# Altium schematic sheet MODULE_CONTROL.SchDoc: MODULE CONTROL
size A3; Author: Silvio Navaretti; CompanyName: ARDUINO; Organization: ARDUINO; SheetNumber: 5; SheetTotal: 51; RevAuthor: Silvio Navaretti
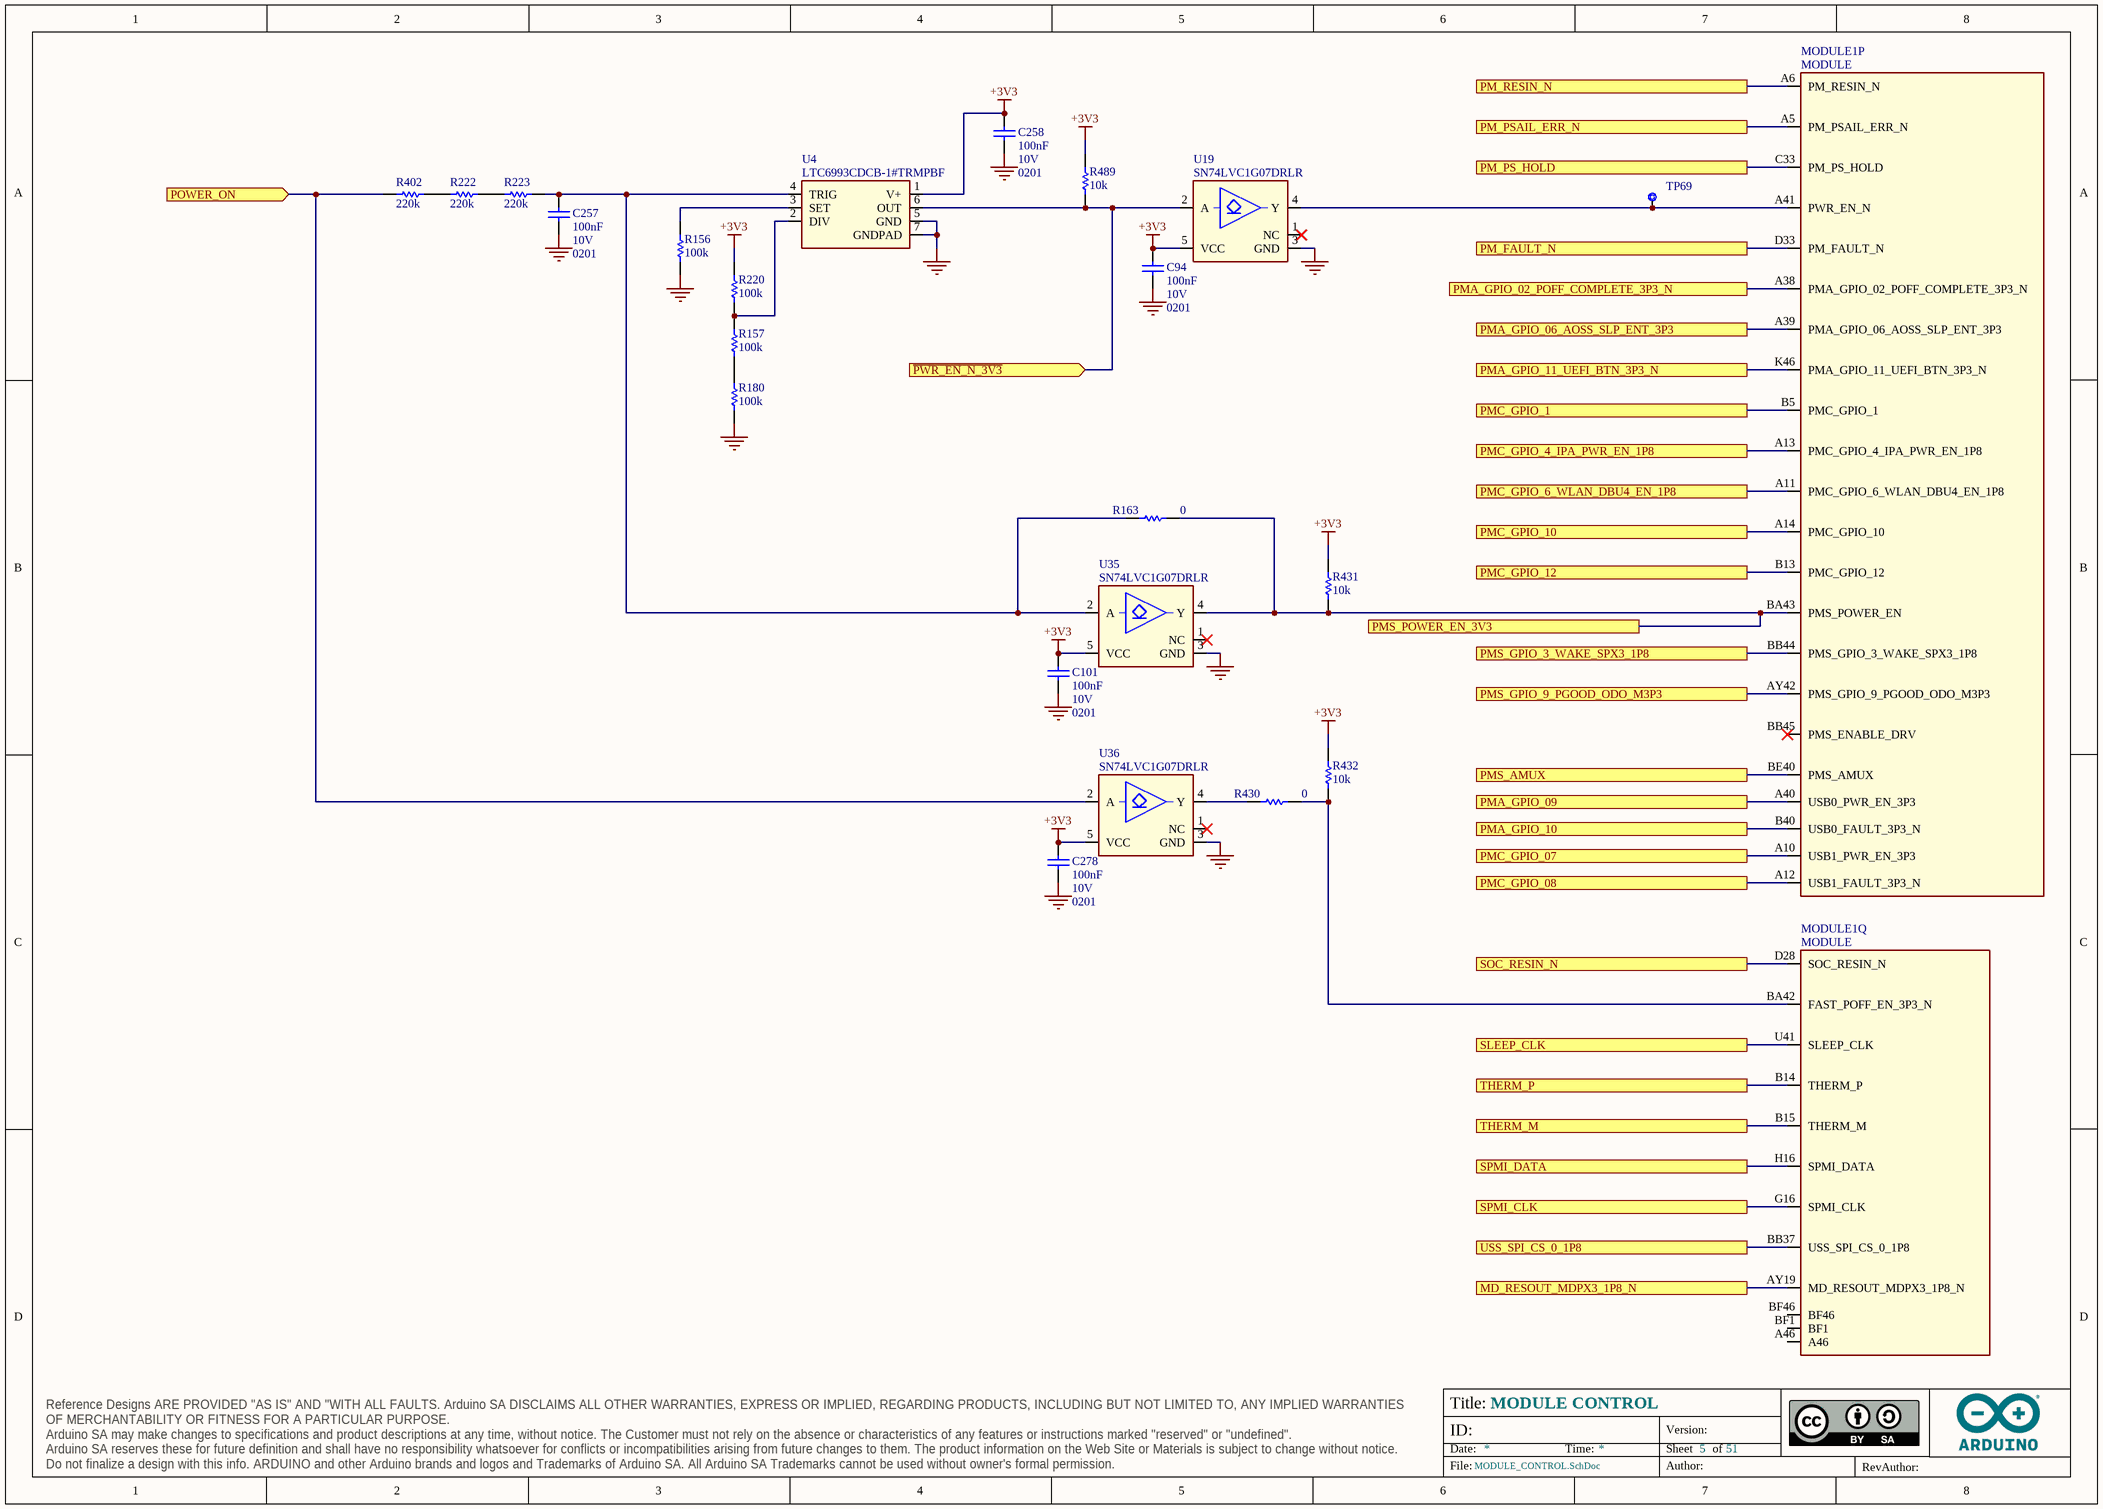
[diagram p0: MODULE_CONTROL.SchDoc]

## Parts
C94  value 100nF  Voltage: 10V  Case Code (Imperial): 0201  [CAP-0201]  (hidden comment: CL03A104KP3NNNC)
C101  value 100nF  Voltage: 10V  Case Code (Imperial): 0201  [CAP-0201]  (hidden comment: CL03A104KP3NNNC)
C257  value 100nF  Voltage: 10V  Case Code (Imperial): 0201  [CAP-0201]  (hidden comment: CL03A104KP3NNNC)
C258  value 100nF  Voltage: 10V  Case Code (Imperial): 0201  [CAP-0201]  (hidden comment: CL03A104KP3NNNC)
C278  value 100nF  Voltage: 10V  Case Code (Imperial): 0201  [CAP-0201]  (hidden comment: CL03A104KP3NNNC)
MODULE1  MODULE  [MODULE]  (parts P,Q of 22)
R156  value 100k  [RES-0201]  (hidden comment: RC0201FR-07100KL)
R157  value 100k  [RES-0201]  (hidden comment: RC0201FR-07100KL)
R163  value 0  [RES-0201]  (hidden comment: CRCW02010000Z0ED)
R180  value 100k  [RES-0201]  (hidden comment: RC0201FR-07100KL)
R220  value 100k  [RES-0201]  (hidden comment: RC0201FR-07100KL)
R222  value 220k  [RES-0201]  (hidden comment: AC0201FR-07220KL)
R223  value 220k  [RES-0201]  (hidden comment: AC0201FR-07220KL)
R402  value 220k  [RES-0201]  (hidden comment: AC0201FR-07220KL)
R430  value 0  [RES-0201]  (hidden comment: CRCW02010000Z0ED)
R431  value 10k  [RES-0201]  (hidden comment: RC0201FR-0710KL)
R432  value 10k  [RES-0201]  (hidden comment: RC0201FR-0710KL)
R489  value 10k  [RES-0201]  (hidden comment: RC0201FR-0710KL)
TP69  Test point 1.00mm  [TP-1.00MM]  (value not drawn)  (no BOM)
U4  LTC6993CDCB-1#TRMPBF  [AD DCB DFN 6 pin 2x3mm pitch 0.5mm]
U19  SN74LVC1G07DRLR  [TI DRL DRL0005A]
U35  SN74LVC1G07DRLR  [TI DRL DRL0005A]
U36  SN74LVC1G07DRLR  [TI DRL DRL0005A]

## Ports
MD_RESOUT_MDPX3_1P8_N, PM_FAULT_N, PM_PS_HOLD, PM_PSAIL_ERR_N, PM_RESIN_N, PMA_GPIO_02_POFF_COMPLETE_3P3_N, PMA_GPIO_06_AOSS_SLP_ENT_3P3, PMA_GPIO_09, PMA_GPIO_10, PMA_GPIO_11_UEFI_BTN_3P3_N, PMC_GPIO_1, PMC_GPIO_4_IPA_PWR_EN_1P8, PMC_GPIO_6_WLAN_DBU4_EN_1P8, PMC_GPIO_07, PMC_GPIO_08, PMC_GPIO_10, PMC_GPIO_12, PMS_AMUX, PMS_GPIO_3_WAKE_SPX3_1P8, PMS_GPIO_9_PGOOD_ODO_M3P3, PMS_POWER_EN_3V3, POWER_ON (in), SLEEP_CLK, SOC_RESIN_N, SPMI_CLK, SPMI_DATA, THERM_M, THERM_P, USS_SPI_CS_0_1P8, ~{PWR_EN_N_3V3} (in)

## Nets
+3V3: C94.2 C101.2 C258.2 C278.2 R220.2 R431.1 R432.1 R489.1 U4.1(V+) U19.5(VCC) U35.5(VCC) U36.5(VCC)
GND: C94.1 C101.1 C257.1 C258.1 C278.1 R156.1 R180.1 U4.5(GND) U4.7(GNDPAD) U19.3(GND) U35.3(GND) U36.3(GND)
MD_RESOUT_MDPX3_1P8_N: MODULE1.AY19(MD_RESOUT_MDPX3_1P8_N) ; port MD_RESOUT_MDPX3_1P8_N
~{PWR_EN_N_3V3}: R489.2 U4.6(OUT) U19.2(A) ; port ~{PWR_EN_N_3V3}
PM_FAULT_N: MODULE1.D33(PM_FAULT_N) ; port PM_FAULT_N
PM_PS_HOLD: MODULE1.C33(PM_PS_HOLD) ; port PM_PS_HOLD
PM_PSAIL_ERR_N: MODULE1.A5(PM_PSAIL_ERR_N) ; port PM_PSAIL_ERR_N
PM_RESIN_N: MODULE1.A6(PM_RESIN_N) ; port PM_RESIN_N
PMA_GPIO_02_POFF_COMPLETE_3P3_N: MODULE1.A38(PMA_GPIO_02_POFF_COMPLETE_3P3_N) ; port PMA_GPIO_02_POFF_COMPLETE_3P3_N
PMA_GPIO_06_AOSS_SLP_ENT_3P3: MODULE1.A39(PMA_GPIO_06_AOSS_SLP_ENT_3P3) ; port PMA_GPIO_06_AOSS_SLP_ENT_3P3
PMA_GPIO_09: MODULE1.A40(USB0_PWR_EN_3P3) ; port PMA_GPIO_09
PMA_GPIO_10: MODULE1.B40(USB0_FAULT_3P3_N) ; port PMA_GPIO_10
PMA_GPIO_11_UEFI_BTN_3P3_N: MODULE1.K46(PMA_GPIO_11_UEFI_BTN_3P3_N) ; port PMA_GPIO_11_UEFI_BTN_3P3_N
PMC_GPIO_1: MODULE1.B5(PMC_GPIO_1) ; port PMC_GPIO_1
PMC_GPIO_4_IPA_PWR_EN_1P8: MODULE1.A13(PMC_GPIO_4_IPA_PWR_EN_1P8) ; port PMC_GPIO_4_IPA_PWR_EN_1P8
PMC_GPIO_6_WLAN_DBU4_EN_1P8: MODULE1.A11(PMC_GPIO_6_WLAN_DBU4_EN_1P8) ; port PMC_GPIO_6_WLAN_DBU4_EN_1P8
PMC_GPIO_07: MODULE1.A10(USB1_PWR_EN_3P3) ; port PMC_GPIO_07
PMC_GPIO_08: MODULE1.A12(USB1_FAULT_3P3_N) ; port PMC_GPIO_08
PMC_GPIO_10: MODULE1.A14(PMC_GPIO_10) ; port PMC_GPIO_10
PMC_GPIO_12: MODULE1.B13(PMC_GPIO_12) ; port PMC_GPIO_12
PMS_AMUX: MODULE1.BE40(PMS_AMUX) ; port PMS_AMUX
PMS_GPIO_3_WAKE_SPX3_1P8: MODULE1.BB44(PMS_GPIO_3_WAKE_SPX3_1P8) ; port PMS_GPIO_3_WAKE_SPX3_1P8
PMS_GPIO_9_PGOOD_ODO_M3P3: MODULE1.AY42(PMS_GPIO_9_PGOOD_ODO_M3P3) ; port PMS_GPIO_9_PGOOD_ODO_M3P3
PMS_POWER_EN_3V3: MODULE1.BA43(PMS_POWER_EN) R163.1 R431.2 U35.4(Y) ; port PMS_POWER_EN_3V3
POWER_ON: R402.2 U36.2(A) ; port POWER_ON
SLEEP_CLK: MODULE1.U41(SLEEP_CLK) ; port SLEEP_CLK
SOC_RESIN_N: MODULE1.D28(SOC_RESIN_N) ; port SOC_RESIN_N
SPMI_CLK: MODULE1.G16(SPMI_CLK) ; port SPMI_CLK
SPMI_DATA: MODULE1.H16(SPMI_DATA) ; port SPMI_DATA
THERM_M: MODULE1.B15(THERM_M) ; port THERM_M
THERM_P: MODULE1.B14(THERM_P) ; port THERM_P
USS_SPI_CS_0_1P8: MODULE1.BB37(USS_SPI_CS_0_1P8) ; port USS_SPI_CS_0_1P8
NetC257_2: C257.2 R163.2 R223.1 U4.4(TRIG) U35.2(A)
NetMODULE1_A41: MODULE1.A41(PWR_EN_N) TP69.X U19.4(Y)
NetMODULE1_BA42: MODULE1.BA42(FAST_POFF_EN_3P3_N) R430.1 R432.2
NetR156_2: R156.2 U4.3(SET)
NetR157_1: R157.1 R180.2
NetR157_2: R157.2 R220.1 U4.2(DIV)
NetR222_1: R222.1 R223.2
NetR222_2: R222.2 R402.1
NetR430_2: R430.2 U36.4(Y)

Not connected (* = marked no-connect by the designer): MODULE1 A46 BB45(PMS_ENABLE_DRV)* BF1 BF46; U19 1(NC)*; U35 1(NC)*; U36 1(NC)*

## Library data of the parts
C94 C101 C257 C258 C278 = C0113-A.6: CAP CHIP 0201 100nF 10% 10V X5R; Manufacturer: Samsung Electro-Mechanics; Code Arduino: C0113
MODULE1 = M0029-A.19: MODULE BGA 1883 balls 57.5x57.5mm; Manufacturer: Qualcomm; Code Arduino: M0029
R156 R157 R180 R220 = R0146-A.21: RES CHIP 0201 100k 1% 1/20W; Manufacturer: Yageo; Power: 50mW; Temperature coefficient: 200ppm; Code Arduino: R0146
R163 R430 = R0140-A.21: RES CHIP 0201 0R; Manufacturer: Vishay; Temperature coefficient: 0ppm; Code Arduino: R0140; Power: 50mW; Tolerance: 0%
R222 R223 R402 = R0199-A.20: RES CHIP 0201 220k 1% 1/20W; Manufacturer: Yageo; Temperature coefficient: 200ppm; Power: 50mW; Code Arduino: R0199
R431 R432 R489 = R0145-A.21: RES CHIP 0201 10k 1% 1/20W; Manufacturer: Yageo; Power: 50mW; Temperature coefficient: 200ppm; Code Arduino: R0145
TP69 = UT0013-A.6: Part Number: This is not a component
U4 = U0524-A.1: IC monostable multivibrator programmable pulse 1us to 33.6 DFN6 2x3mm; Manufacturer: Analog Devices; Code Arduino: U0524
U19 U35 U36 = U0494-A.2: IC buffer open drain, 1.65V to 5.5V, 32mA sink current, SOT-5X3 1.6mmx1.6mm; Manufacturer: Texas Instruments; Code Arduino: U0494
